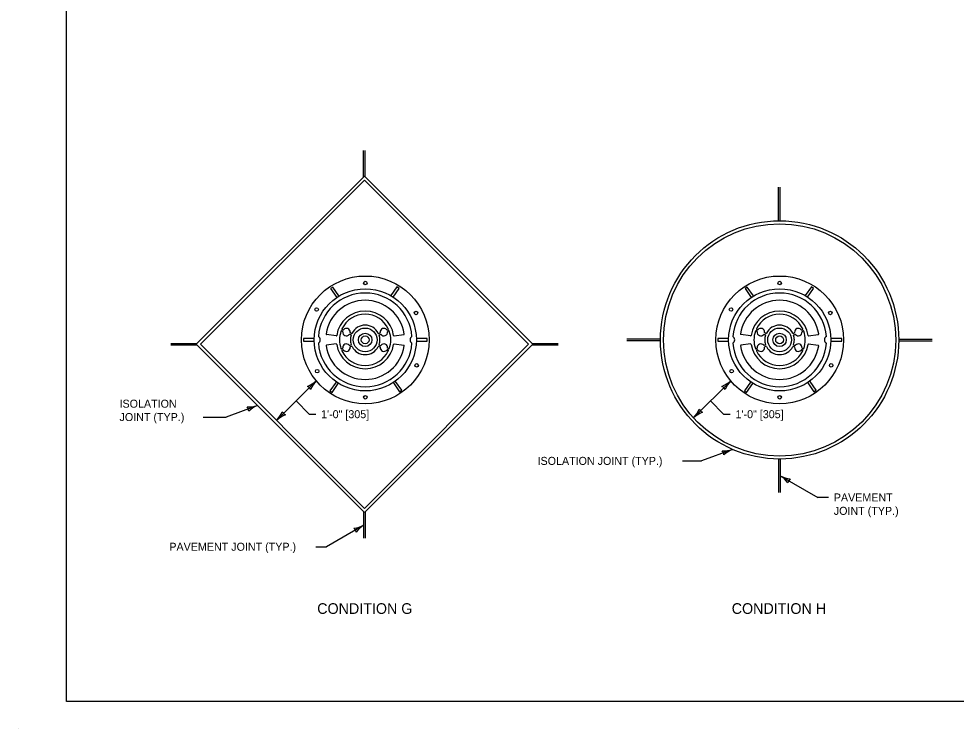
# Model space of a CAD drawing. Extents: x 49991.4 to 50021, y 49987.6 to 50011.4.
# Drawn here: x 49999.02 to 50006.05, y 49987.6 to 49992.91 of the extents above; entities that cross this region are included whole.
import ezdxf

# ---------------------------------------------------------------- set-up
doc = ezdxf.new("R2010")
doc.units = 0
for name, color, linetype in [('Level 1', 7, 'Continuous'), ('Level 2', 7, 'Continuous'), ('Level 3', 7, 'Continuous'), ('Level 62', 7, 'Continuous'), ('W35', 7, 'Continuous')]:
    doc.layers.add(name, color=color, linetype=linetype)

msp = doc.modelspace()

# ---------------------------------------------------------------- linework, layer by layer
at = {"layer": 'Level 1'}
for p, q in [((50001.6081, 49991.7286), (50001.6081, 49991.927)), ((50001.6201, 49991.7312), (50001.6201, 49991.927)), ((50004.7182, 49991.4007), (50004.7182, 49991.652)), ((50004.7302, 49991.4007), (50004.7302, 49991.652)), ((50001.4025, 49990.5388), (50001.3303, 49990.5489)), ((50001.4495, 49990.5727), (50001.4441, 49990.575)), ((50001.4539, 49990.5832), (50001.4484, 49990.5854)), ((50001.5126, 49990.5466), (50001.5057, 49990.5494)), ((50001.5169, 49990.5571), (50001.5101, 49990.5599)), ((50001.7234, 49990.5571), (50001.7302, 49990.5599)), ((50001.7277, 49990.5466), (50001.7346, 49990.5494)), ((50001.7864, 49990.5832), (50001.7919, 49990.5854)), ((50001.7908, 49990.5727), (50001.7962, 49990.575)), ((50001.8378, 49990.5388), (50001.91, 49990.5489)), ((50004.5079, 49990.5388), (50004.4357, 49990.5489)), ((50004.5549, 49990.5727), (50004.5495, 49990.575)), ((50004.5592, 49990.5832), (50004.5538, 49990.5854)), ((50004.6179, 49990.5466), (50004.6111, 49990.5494)), ((50004.6223, 49990.5571), (50004.6154, 49990.5599)), ((50004.8288, 49990.5571), (50004.8356, 49990.5599)), ((50004.8331, 49990.5466), (50004.84, 49990.5494)), ((50004.8918, 49990.5832), (50004.8972, 49990.5854)), ((50004.8962, 49990.5727), (50004.9016, 49990.575)), ((50004.9432, 49990.5388), (50005.0154, 49990.5489)), ((50000.3593, 49990.4797), (50000.1635, 49990.4797)), ((50000.3619, 49990.4677), (50000.1635, 49990.4677)), ((50001.4025, 49990.4776), (50001.3303, 49990.4674)), ((50001.5126, 49990.4698), (50001.5057, 49990.4669)), ((50001.5169, 49990.4593), (50001.5101, 49990.4564)), ((50001.7234, 49990.4593), (50001.7302, 49990.4564)), ((50001.7277, 49990.4698), (50001.7346, 49990.4669)), ((50001.8378, 49990.4776), (50001.91, 49990.4674)), ((50003.0674, 49990.4677), (50002.869, 49990.4677)), ((50003.0674, 49990.4797), (50002.8716, 49990.4797)), ((50003.8329, 49990.5129), (50003.5817, 49990.5129)), ((50003.833, 49990.5009), (50003.5817, 49990.5009)), ((50004.5079, 49990.4776), (50004.4357, 49990.4674)), ((50004.6179, 49990.4698), (50004.6111, 49990.4669)), ((50004.6223, 49990.4593), (50004.6154, 49990.4564)), ((50004.8288, 49990.4593), (50004.8356, 49990.4564)), ((50004.8331, 49990.4698), (50004.84, 49990.4669)), ((50004.9432, 49990.4776), (50005.0154, 49990.4674)), ((50005.6181, 49990.5129), (50005.8693, 49990.5129)), ((50005.6181, 49990.5009), (50005.8693, 49990.5009)), ((50001.4495, 49990.4436), (50001.4441, 49990.4414)), ((50001.4539, 49990.4331), (50001.4484, 49990.4309)), ((50001.7864, 49990.4331), (50001.7919, 49990.4309)), ((50001.7908, 49990.4436), (50001.7962, 49990.4414)), ((50004.5549, 49990.4436), (50004.5495, 49990.4414)), ((50004.5592, 49990.4331), (50004.5538, 49990.4309)), ((50004.8918, 49990.4331), (50004.8972, 49990.4309)), ((50004.8962, 49990.4436), (50004.9016, 49990.4414)), ((50004.7182, 49989.6156), (50004.7182, 49989.3643)), ((50004.7302, 49989.6156), (50004.7302, 49989.3643)), ((50001.6108, 49989.0231), (50001.6108, 49989.2189)), ((50001.6228, 49989.0231), (50001.6228, 49989.2215)), ((49999.0245, 49987.5988), (49999.0245, 49987.5988))]:
    msp.add_line(p, q, dxfattribs=at)
for points in [[(49999.3835, 49998.9992), (50016.7501, 49998.9992), (50016.7501, 49987.7988), (49999.3835, 49987.7988)], [(50001.6155, 49991.7359), (50002.8763, 49990.4751), (50001.6155, 49989.2142), (50000.3546, 49990.4751)], [(50001.6155, 49991.7041), (50000.3864, 49990.4751), (50001.6155, 49989.246), (50002.8445, 49990.4751)]]:
    msp.add_lwpolyline(points, close=True, dxfattribs=at)
for points in [[(50001.424, 49990.838), (50001.378, 49990.9036), (50001.3616, 49990.8921), (50001.4076, 49990.8265)], [(50001.424, 49990.838), (50001.378, 49990.9036), (50001.3616, 49990.8921), (50001.4076, 49990.8265)], [(50001.8289, 49990.8281), (50001.8749, 49990.8937), (50001.8585, 49990.9052), (50001.8125, 49990.8396)], [(50001.8289, 49990.8281), (50001.8749, 49990.8937), (50001.8585, 49990.9052), (50001.8125, 49990.8396)], [(50004.5293, 49990.838), (50004.4834, 49990.9036), (50004.467, 49990.8921), (50004.513, 49990.8265)], [(50004.5293, 49990.838), (50004.4834, 49990.9036), (50004.467, 49990.8921), (50004.513, 49990.8265)], [(50004.9343, 49990.8281), (50004.9803, 49990.8937), (50004.9639, 49990.9052), (50004.9179, 49990.8396)], [(50004.9343, 49990.8281), (50004.9803, 49990.8937), (50004.9639, 49990.9052), (50004.9179, 49990.8396)], [(50001.2384, 49990.5187), (50001.1583, 49990.5187), (50001.1583, 49990.4987), (50001.2384, 49990.4987)], [(50002.0058, 49990.4976), (50002.0859, 49990.4976), (50002.0859, 49990.5176), (50002.0058, 49990.5176)], [(50004.3438, 49990.5187), (50004.2637, 49990.5187), (50004.2637, 49990.4987), (50004.3438, 49990.4987)], [(50005.1112, 49990.4976), (50005.1913, 49990.4976), (50005.1913, 49990.5176), (50005.1112, 49990.5176)], [(50001.4022, 49990.1918), (50001.3563, 49990.1261), (50001.3727, 49990.1146), (50001.4186, 49990.1803)], [(50001.4022, 49990.1918), (50001.3563, 49990.1261), (50001.3727, 49990.1146), (50001.4186, 49990.1803)], [(50001.8316, 49990.1857), (50001.8776, 49990.12), (50001.894, 49990.1315), (50001.848, 49990.1971)], [(50001.8316, 49990.1857), (50001.8776, 49990.12), (50001.894, 49990.1315), (50001.848, 49990.1971)], [(50004.5076, 49990.1918), (50004.4617, 49990.1261), (50004.4781, 49990.1146), (50004.524, 49990.1803)], [(50004.5076, 49990.1918), (50004.4617, 49990.1261), (50004.4781, 49990.1146), (50004.524, 49990.1803)], [(50004.937, 49990.1857), (50004.983, 49990.12), (50004.9994, 49990.1315), (50004.9534, 49990.1971)], [(50004.937, 49990.1857), (50004.983, 49990.12), (50004.9994, 49990.1315), (50004.9534, 49990.1971)]]:
    msp.add_lwpolyline(points, dxfattribs=at)
for centre, radius in [((50004.7255, 49990.5082), 0.8926), ((50004.7255, 49990.5082), 0.8701), ((50001.621, 49990.5084), 0.4784), ((50001.621, 49990.5084), 0.4784), ((50001.621, 49990.9342), 0.0131), ((50004.7264, 49990.5084), 0.4784), ((50004.7264, 49990.5084), 0.4784), ((50004.7264, 49990.9342), 0.0131), ((50001.621, 49990.5084), 0.3827), ((50001.621, 49990.5084), 0.3827), ((50004.7264, 49990.5084), 0.3827), ((50004.7264, 49990.5084), 0.3827), ((50001.2564, 49990.7362), 0.0131), ((50004.3618, 49990.7362), 0.0131), ((50002.0009, 49990.7098), 0.0131), ((50005.1062, 49990.7098), 0.0131), ((50001.6201, 49990.5082), 0.0888), ((50004.7255, 49990.5082), 0.0888), ((50001.6201, 49990.5082), 0.0503), ((50001.6201, 49990.5082), 0.0293), ((50004.7255, 49990.5082), 0.0503), ((50004.7255, 49990.5082), 0.0293), ((50002.0062, 49990.3175), 0.0131), ((50005.1116, 49990.3175), 0.0131), ((50001.2604, 49990.2743), 0.0131), ((50004.3658, 49990.2743), 0.0131), ((50001.621, 49990.0784), 0.0131), ((50004.7264, 49990.0784), 0.0131)]:
    msp.add_circle(centre, radius, dxfattribs=at)
for centre, radius, start, end in [((50001.6201, 49990.5082), 0.3512, 4.13676, 175.86322), ((50001.6201, 49990.5082), 0.2965, 8.74918, 171.25082), ((50004.7255, 49990.5082), 0.3512, 4.13676, 175.86322), ((50004.7255, 49990.5082), 0.2965, 8.74918, 171.25082), ((50001.6201, 49990.5082), 0.216, 8.99765, 171.00235), ((50001.6201, 49990.5082), 0.1922, 90, 154.63538), ((50001.6201, 49990.5082), 0.1922, 25.36457, 90), ((50004.7255, 49990.5082), 0.216, 8.99765, 171.00235), ((50004.7255, 49990.5082), 0.1922, 90, 154.63538), ((50004.7255, 49990.5082), 0.1922, 25.36457, 90), ((50001.4499, 49990.5889), 0.00374, 154.63452, 247.50047), ((50001.4798, 49990.5663), 0.0281, 354.70438, 140.29581), ((50001.6201, 49990.5082), 0.1107, 90, 152.78109), ((50001.6201, 49990.5082), 0.1107, 27.21891, 90), ((50001.7605, 49990.5663), 0.0281, 39.70419, 185.29564), ((50001.7904, 49990.5889), 0.00374, 292.50097, 25.36548), ((50004.5552, 49990.5889), 0.00374, 154.63452, 247.50047), ((50004.5852, 49990.5663), 0.0281, 354.70438, 140.29581), ((50004.7255, 49990.5082), 0.1107, 90, 152.78109), ((50004.7255, 49990.5082), 0.1107, 27.21891, 90), ((50004.8659, 49990.5663), 0.0281, 39.70419, 185.29564), ((50004.8958, 49990.5889), 0.00374, 292.50097, 25.36548), ((50001.254, 49990.5082), 0.0299, 302.04668, 57.95332), ((50001.3308, 49990.5527), 0.00383, 171.25152, 262.00056), ((50001.403, 49990.5425), 0.00383, 262.00056, 351.00138), ((50001.6201, 49990.5082), 0.1922, 160.36454, 179.99994), ((50001.4426, 49990.5715), 0.00374, 67.50047, 160.36529), ((50001.4481, 49990.5692), 0.00374, 354.70324, 67.50047), ((50001.4798, 49990.5663), 0.0281, 174.70396, 320.29581), ((50001.4553, 49990.5867), 0.00374, 247.50047, 320.29757), ((50001.5043, 49990.546), 0.00374, 67.50047, 140.29757), ((50001.5115, 49990.5634), 0.00374, 174.70324, 247.50047), ((50001.6201, 49990.5082), 0.1107, 162.2189, 180), ((50001.5111, 49990.5431), 0.00374, 342.21869, 67.50047), ((50001.5183, 49990.5605), 0.00374, 247.50047, 332.78143), ((50001.722, 49990.5605), 0.00374, 207.21857, 292.49953), ((50001.7292, 49990.5431), 0.00374, 112.49953, 197.78178), ((50001.6201, 49990.5082), 0.1107, 0, 17.7811), ((50001.7288, 49990.5634), 0.00374, 292.50097, 5.2969), ((50001.736, 49990.546), 0.00374, 39.70343, 112.50097), ((50001.7605, 49990.5663), 0.0281, 219.70419, 5.29606), ((50001.785, 49990.5867), 0.00374, 219.70343, 292.50097), ((50001.7922, 49990.5692), 0.00374, 112.50097, 185.2969), ((50001.7976, 49990.5715), 0.00374, 19.63471, 112.50097), ((50001.6201, 49990.5082), 0.1922, 0, 19.63545), ((50001.8373, 49990.5425), 0.00383, 188.99862, 277.99944), ((50001.9094, 49990.5527), 0.00383, 277.99944, 8.74848), ((50001.9863, 49990.5082), 0.0299, 122.04687, 237.95313), ((50004.3594, 49990.5082), 0.0299, 302.04668, 57.95332), ((50004.4362, 49990.5527), 0.00383, 171.25152, 262.00056), ((50004.5084, 49990.5425), 0.00383, 262.00056, 351.00138), ((50004.7255, 49990.5082), 0.1922, 160.36454, 179.99994), ((50004.548, 49990.5715), 0.00374, 67.50047, 160.36529), ((50004.5535, 49990.5692), 0.00374, 354.70324, 67.50047), ((50004.5852, 49990.5663), 0.0281, 174.70396, 320.29581), ((50004.5607, 49990.5867), 0.00374, 247.50047, 320.29757), ((50004.6097, 49990.546), 0.00374, 67.50047, 140.29757), ((50004.6169, 49990.5634), 0.00374, 174.70324, 247.50047), ((50004.7255, 49990.5082), 0.1107, 162.2189, 180), ((50004.6165, 49990.5431), 0.00374, 342.21869, 67.50047), ((50004.6237, 49990.5605), 0.00374, 247.50047, 332.78143), ((50004.8273, 49990.5605), 0.00374, 207.21857, 292.49953), ((50004.8345, 49990.5431), 0.00374, 112.49953, 197.78178), ((50004.7255, 49990.5082), 0.1107, 0, 17.7811), ((50004.8342, 49990.5634), 0.00374, 292.50097, 5.2969), ((50004.8414, 49990.546), 0.00374, 39.70343, 112.50097), ((50004.8659, 49990.5663), 0.0281, 219.70419, 5.29606), ((50004.8904, 49990.5867), 0.00374, 219.70343, 292.50097), ((50004.8976, 49990.5692), 0.00374, 112.50097, 185.2969), ((50004.903, 49990.5715), 0.00374, 19.63471, 112.50097), ((50004.7255, 49990.5082), 0.1922, 0, 19.63545), ((50004.9426, 49990.5425), 0.00383, 188.99862, 277.99944), ((50005.0148, 49990.5527), 0.00383, 277.99944, 8.74848), ((50005.0916, 49990.5082), 0.0299, 122.04687, 237.95313), ((50001.6201, 49990.5082), 0.3512, 184.13678, 355.86324), ((50001.3308, 49990.4636), 0.00383, 97.99944, 188.74848), ((50001.6201, 49990.5082), 0.2965, 188.74918, 351.25086), ((50001.403, 49990.4738), 0.00383, 8.99862, 97.99944), ((50001.6201, 49990.5082), 0.216, 188.99765, 351.0024), ((50001.6201, 49990.5082), 0.1922, 179.99994, 199.63538), ((50001.4481, 49990.4471), 0.00374, 292.49953, 5.29676), ((50001.4798, 49990.45), 0.0281, 39.70419, 185.29604), ((50001.4798, 49990.45), 0.0281, 219.70419, 5.29562), ((50001.5043, 49990.4704), 0.00374, 219.70243, 292.49953), ((50001.5115, 49990.453), 0.00374, 112.49953, 185.29676), ((50001.6201, 49990.5082), 0.1107, 180, 197.781), ((50001.5111, 49990.4732), 0.00374, 292.49953, 17.78131), ((50001.5183, 49990.4558), 0.00374, 27.21857, 112.49953), ((50001.6201, 49990.5082), 0.1107, 207.21891, 270), ((50001.6201, 49990.5082), 0.1107, 270, 332.78109), ((50001.722, 49990.4558), 0.00374, 67.50047, 152.78143), ((50001.7292, 49990.4732), 0.00374, 162.21822, 247.50047), ((50001.6201, 49990.5082), 0.1107, 342.2189, 0), ((50001.7288, 49990.453), 0.00374, 354.7031, 67.49903), ((50001.7605, 49990.45), 0.0281, 174.70436, 320.29581), ((50001.736, 49990.4704), 0.00374, 247.49903, 320.29657), ((50001.7605, 49990.45), 0.0281, 354.70394, 140.29581), ((50001.7922, 49990.4471), 0.00374, 174.7031, 247.49903), ((50001.6201, 49990.5082), 0.1922, 340.36455, 0), ((50001.8373, 49990.4738), 0.00383, 82.00056, 171.00138), ((50001.9094, 49990.4636), 0.00383, 351.25152, 82.00056), ((50004.7255, 49990.5082), 0.3512, 184.13678, 355.86324), ((50004.4362, 49990.4636), 0.00383, 97.99944, 188.74848), ((50004.7255, 49990.5082), 0.2965, 188.74918, 351.25086), ((50004.5084, 49990.4738), 0.00383, 8.99862, 97.99944), ((50004.7255, 49990.5082), 0.216, 188.99765, 351.0024), ((50004.7255, 49990.5082), 0.1922, 179.99994, 199.63538), ((50004.5535, 49990.4471), 0.00374, 292.49953, 5.29676), ((50004.5852, 49990.45), 0.0281, 39.70419, 185.29604), ((50004.5852, 49990.45), 0.0281, 219.70419, 5.29562), ((50004.6097, 49990.4704), 0.00374, 219.70243, 292.49953), ((50004.6169, 49990.453), 0.00374, 112.49953, 185.29676), ((50004.7255, 49990.5082), 0.1107, 180, 197.781), ((50004.6165, 49990.4732), 0.00374, 292.49953, 17.78131), ((50004.6237, 49990.4558), 0.00374, 27.21857, 112.49953), ((50004.7255, 49990.5082), 0.1107, 207.21891, 270), ((50004.7255, 49990.5082), 0.1107, 270, 332.78109), ((50004.8273, 49990.4558), 0.00374, 67.50047, 152.78143), ((50004.8345, 49990.4732), 0.00374, 162.21822, 247.50047), ((50004.7255, 49990.5082), 0.1107, 342.2189, 0), ((50004.8342, 49990.453), 0.00374, 354.7031, 67.49903), ((50004.8659, 49990.45), 0.0281, 174.70436, 320.29581), ((50004.8414, 49990.4704), 0.00374, 247.49903, 320.29657), ((50004.8659, 49990.45), 0.0281, 354.70394, 140.29581), ((50004.8976, 49990.4471), 0.00374, 174.7031, 247.49903), ((50004.7255, 49990.5082), 0.1922, 340.36455, 0), ((50004.9426, 49990.4738), 0.00383, 82.00056, 171.00138), ((50005.0148, 49990.4636), 0.00383, 351.25152, 82.00056), ((50001.4426, 49990.4448), 0.00374, 199.63471, 292.49953), ((50001.4499, 49990.4274), 0.00374, 112.49953, 205.36548), ((50001.6201, 49990.5082), 0.1922, 205.36462, 270), ((50001.4553, 49990.4297), 0.00374, 39.70243, 112.49953), ((50001.6201, 49990.5082), 0.1922, 270, 334.63543), ((50001.785, 49990.4297), 0.00374, 67.49903, 140.29657), ((50001.7904, 49990.4274), 0.00374, 334.63452, 67.49903), ((50001.7976, 49990.4448), 0.00374, 247.49903, 340.36529), ((50004.548, 49990.4448), 0.00374, 199.63471, 292.49953), ((50004.5552, 49990.4274), 0.00374, 112.49953, 205.36548), ((50004.7255, 49990.5082), 0.1922, 205.36462, 270), ((50004.5607, 49990.4297), 0.00374, 39.70243, 112.49953), ((50004.7255, 49990.5082), 0.1922, 270, 334.63543), ((50004.8904, 49990.4297), 0.00374, 67.49903, 140.29657), ((50004.8958, 49990.4274), 0.00374, 334.63452, 67.49903), ((50004.903, 49990.4448), 0.00374, 247.49903, 340.36529)]:
    msp.add_arc(centre, radius, start, end, dxfattribs=at)
at = {"layer": 'Level 2'}
for p, q in [((50001.2537, 49990.2018), (50000.9567, 49989.9048)), ((50004.3591, 49990.2018), (50004.081, 49989.9237)), ((50000.8132, 49990.0164), (50000.5791, 49989.9305)), ((50000.4055, 49989.9302), (50000.5791, 49989.9305)), ((50004.3735, 49989.6879), (50004.1394, 49989.602)), ((50003.9973, 49989.6017), (50004.1394, 49989.602)), ((50004.7302, 49989.49), (50005.0117, 49989.3275)), ((50005.0917, 49989.3275), (50005.0117, 49989.3275)), ((50001.6108, 49989.121), (50001.3293, 49988.9585)), ((50001.2493, 49988.9585), (50001.3293, 49988.9585))]:
    msp.add_line(p, q, dxfattribs=at)
at = {"layer": 'Level 3'}
for p, q in [((50001.1029, 49990.051), (50001.1998, 49989.9515)), ((50004.2082, 49990.051), (50004.3051, 49989.9515)), ((50001.1998, 49989.9515), (50001.2499, 49989.9515)), ((50004.3051, 49989.9515), (50004.3553, 49989.9515))]:
    msp.add_line(p, q, dxfattribs=at)
for centre, radius, start, end in [((50001.1031, 49990.3654), 0.2223, 292.45601, 312.63952), ((50001.4264, 49990.0454), 0.233, 137.82731, 157.07716), ((50004.2085, 49990.3654), 0.2223, 292.45601, 312.63952), ((50004.5318, 49990.0454), 0.233, 137.82731, 157.07716), ((50001.1631, 49990.1112), 0.0548, 27.13882, 62.86118), ((50004.2684, 49990.1112), 0.0548, 27.13882, 62.86118), ((50000.7453, 49990.2281), 0.2223, 267.6176, 287.80111), ((50000.6929, 49989.9722), 0.0548, 2.30041, 38.02277), ((50000.9042, 49989.8019), 0.233, 112.9889, 132.23875), ((50000.784, 49990.0612), 0.233, 317.82731, 337.07716), ((50001.0473, 49989.9954), 0.0548, 207.13882, 242.86118), ((50003.9083, 49990.0801), 0.233, 317.82731, 337.07716), ((50004.2316, 49989.7601), 0.2223, 112.45601, 132.63952), ((50004.1716, 49990.0144), 0.0548, 207.13882, 242.86118), ((50001.1073, 49989.7412), 0.2223, 112.45601, 132.63952), ((50004.3056, 49989.8996), 0.2223, 267.6176, 287.80111), ((50004.2532, 49989.6437), 0.0548, 2.30041, 38.02277), ((50004.4645, 49989.4734), 0.233, 112.9889, 132.23875), ((50004.6112, 49989.3022), 0.2223, 37.45601, 57.63952), ((50004.8366, 49989.6973), 0.233, 242.82731, 262.07716), ((50004.8412, 49989.4259), 0.0548, 132.13882, 167.86118), ((50001.5076, 49989.318), 0.2223, 277.45601, 297.63952), ((50001.7371, 49988.9252), 0.233, 122.82731, 142.07716), ((50001.4997, 49989.0569), 0.0548, 12.13882, 47.86118)]:
    msp.add_arc(centre, radius, start, end, dxfattribs=at)
at = {"layer": 'Level 62'}
msp.add_line((50003.0674, 49990.4797), (50002.8716, 49990.4797), dxfattribs=at)
at = {"layer": 'W35'}
for points in [[(50001.2384, 49990.5187), (50001.1583, 49990.5187), (50001.1583, 49990.4987), (50001.2384, 49990.4987)], [(50002.0058, 49990.4976), (50002.0859, 49990.4976), (50002.0859, 49990.5176), (50002.0058, 49990.5176)], [(50004.3438, 49990.5187), (50004.2637, 49990.5187), (50004.2637, 49990.4987), (50004.3438, 49990.4987)], [(50005.1112, 49990.4976), (50005.1913, 49990.4976), (50005.1913, 49990.5176), (50005.1112, 49990.5176)]]:
    msp.add_lwpolyline(points, dxfattribs=at)

# ---------------------------------------------------------------- texts
at = {"layer": 'Level 2'}
for s, p in [('ISOLATION ', (49999.7797, 49990.0001)), ('JOINT (TYP.)', (49999.7797, 49989.9001)), ('ISOLATION JOINT (TYP.)', (50002.9119, 49989.5717))]:
    msp.add_text(s, height=0.06, rotation=360, dxfattribs=at).set_placement(p)
for s, height, p in [('1\'-0" [305]', 0.06, (50001.2899, 49989.9215)), ('1\'-0" [305]', 0.06, (50004.3953, 49989.9215)), ('PAVEMENT', 0.06, (50005.1317, 49989.2975)), ('JOINT (TYP.)', 0.06, (50005.1317, 49989.1975)), ('PAVEMENT JOINT (TYP.)', 0.06, (50000.153, 49988.9285)), ('CONDITION G', 0.08, (50001.2609, 49988.4555)), ('CONDITION H', 0.08, (50004.3668, 49988.4555))]:
    msp.add_text(s, height=height, dxfattribs=at).set_placement(p)

doc.saveas('drawing.dxf')
